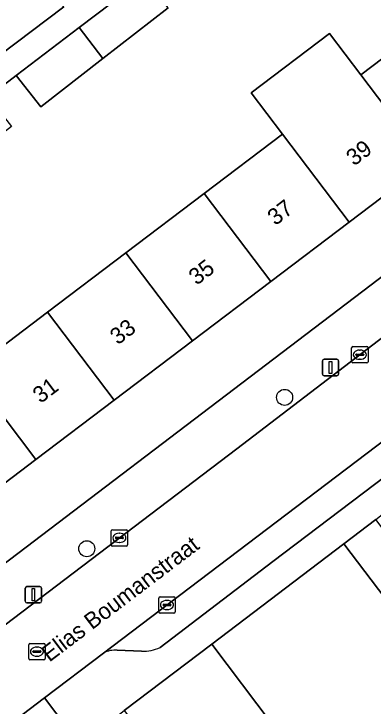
# Model space of a CAD drawing. Extents: x 160030 to 160839, y 385325 to 386450.
# Drawn here: x 160320.85 to 160342.79, y 385850.63 to 385892.89 of the extents above; entities that cross this region are included whole.
import ezdxf

# ---------------------------------------------------------------- set-up
doc = ezdxf.new("R2010")
doc.units = 0
for name, color, linetype in [('IMGEO_Boom', 7, 'Continuous'), ('IMGEO_Erf', 7, 'Continuous'), ('IMGEO_Groenvoorziening', 7, 'Continuous'), ('IMGEO_Kolk', 7, 'Continuous'), ('IMGEO_Lichtmast', 7, 'Continuous'), ('IMGEO_Muur', 7, 'Continuous'), ('IMGEO_Openbare_ruimte_label', 7, 'Continuous'), ('IMGEO_Pand', 7, 'Continuous'), ('IMGEO_Pand_nummerreeks', 7, 'Continuous'), ('IMGEO_Parkeervlak_open', 7, 'Continuous'), ('IMGEO_Rijbaan_lokaal_open', 7, 'Continuous'), ('IMGEO_Rioolput', 7, 'Continuous'), ('IMGEO_Voetpad_open', 7, 'Continuous')]:
    doc.layers.add(name, color=color, linetype=linetype)

msp = doc.modelspace()

# ---------------------------------------------------------------- linework, layer by layer
at = {"layer": 'IMGEO_Boom'}
for centre in [(160337.388, 385869.482), (160325.309, 385860.242)]:
    msp.add_circle(centre, 0.489, dxfattribs=at)
at = {"layer": 'IMGEO_Erf'}
for points in [[(160294.063, 385852.843), (160298.997, 385856.578), (160303.779, 385860.2), (160308.563, 385863.822), (160313.347, 385867.444), (160318.13, 385871.066), (160322.914, 385874.688), (160327.697, 385878.309), (160332.481, 385881.931), (160337.264, 385885.553), (160335.354, 385888.075), (160340.138, 385891.697), (160342.048, 385889.175), (160346.831, 385892.796), (160351.765, 385896.532)], [(160330.268, 385893.263), (160326.279, 385890.159), (160322.499, 385887.218), (160321.004, 385889.138), (160319.29, 385887.834), (160320.701, 385886.02), (160316.695, 385882.903), (160312.932, 385879.975), (160311.453, 385881.876), (160309.511, 385880.442), (160310.707, 385878.818), (160306.883, 385875.948), (160303.08, 385873.095), (160301.888, 385874.626), (160300.199, 385873.289), (160301.566, 385871.532), (160297.525, 385868.388)], [(160356.339, 385890.539), (160355.831, 385891.162), (160350.897, 385887.426), (160346.114, 385883.805), (160341.33, 385880.183), (160336.547, 385876.561), (160331.763, 385872.939), (160326.98, 385869.318), (160322.196, 385865.696), (160317.412, 385862.073), (160312.629, 385858.452), (160307.845, 385854.83), (160303.062, 385851.208), (160298.129, 385847.473), (160300.518, 385844.329), (160355.835, 385886.372)], [(160351.187, 385847.126), (160348.331, 385850.871), (160345.262, 385854.895), (160347.23, 385856.396), (160345.903, 385858.136), (160343.947, 385856.654), (160340.997, 385860.55), (160332.936, 385854.418), (160336.632, 385849.537)]]:
    msp.add_lwpolyline(points, dxfattribs=at)
at = {"layer": 'IMGEO_Groenvoorziening'}
msp.add_lwpolyline([(160321.143, 385833.325), (160328.543, 385823.58), (160338.075, 385830.835), (160322.717, 385851.129), (160316.136, 385846.137)], dxfattribs=at)
at = {"layer": 'IMGEO_Kolk'}
for p, q in [((160341.48, 385871.658), (160341.48, 385872.51)), ((160341.555, 385872.584), (160342.407, 385872.584)), ((160342.481, 385872.51), (160342.481, 385871.658)), ((160341.739, 385872.078), (160341.739, 385872.09)), ((160342.177, 385872.041), (160341.779, 385872.041)), ((160341.782, 385872.127), (160342.18, 385872.127)), ((160341.968, 385872.364), (160341.993, 385872.364)), ((160342.223, 385872.09), (160342.223, 385872.078)), ((160342.407, 385871.584), (160341.555, 385871.584)), ((160341.991, 385871.804), (160341.966, 385871.804)), ((160326.872, 385861.404), (160327.724, 385861.404)), ((160326.797, 385860.478), (160326.797, 385861.33)), ((160327.285, 385861.184), (160327.31, 385861.184)), ((160327.798, 385861.33), (160327.798, 385860.478)), ((160327.056, 385860.898), (160327.056, 385860.91)), ((160327.494, 385860.861), (160327.096, 385860.861)), ((160327.099, 385860.947), (160327.497, 385860.947)), ((160327.308, 385860.624), (160327.283, 385860.624)), ((160327.54, 385860.91), (160327.54, 385860.898)), ((160327.724, 385860.404), (160326.872, 385860.404)), ((160329.703, 385856.381), (160329.703, 385857.233)), ((160329.778, 385857.307), (160330.63, 385857.307)), ((160330.704, 385857.233), (160330.704, 385856.381)), ((160329.962, 385856.801), (160329.962, 385856.813)), ((160330.4, 385856.764), (160330.002, 385856.764)), ((160330.005, 385856.85), (160330.403, 385856.85)), ((160330.191, 385857.087), (160330.216, 385857.087)), ((160330.446, 385856.813), (160330.446, 385856.801)), ((160330.63, 385856.307), (160329.778, 385856.307)), ((160330.214, 385856.527), (160330.189, 385856.527))]:
    msp.add_line(p, q, dxfattribs=at)
for points in [[(160341.48, 385871.658), (160341.48, 385872.51)], [(160341.555, 385872.584), (160342.407, 385872.584)], [(160342.481, 385872.51), (160342.481, 385871.658)], [(160342.407, 385871.584), (160341.555, 385871.584)], [(160326.872, 385861.404), (160327.724, 385861.404)], [(160326.797, 385860.478), (160326.797, 385861.33)], [(160327.798, 385861.33), (160327.798, 385860.478)], [(160327.724, 385860.404), (160326.872, 385860.404)], [(160329.703, 385856.381), (160329.703, 385857.233)], [(160329.778, 385857.307), (160330.63, 385857.307)], [(160330.704, 385857.233), (160330.704, 385856.381)], [(160330.63, 385856.307), (160329.778, 385856.307)]]:
    msp.add_lwpolyline(points, dxfattribs=at)
for centre, radius, start, end in [((160341.557, 385872.508), 0.0765, 91.552, 178.448), ((160341.557, 385872.508), 0.0765, 91.552, 178.448), ((160342.405, 385872.508), 0.0765, 1.552, 88.448), ((160342.405, 385872.508), 0.0765, 1.552, 88.448), ((160341.779, 385872.087), 0.0403, 85.8775, 175.7526), ((160341.776, 385872.077), 0.0366, 178.938, 274.7102), ((160342.18, 385872.084), 0.043, 264.8664, 352.4533), ((160342.184, 385872.089), 0.0386, 1.7309, 96.639), ((160341.557, 385871.66), 0.0765, 181.552, 268.448), ((160341.557, 385871.66), 0.0765, 181.552, 268.448), ((160342.405, 385871.66), 0.0765, 271.552, 358.448), ((160342.405, 385871.66), 0.0765, 271.552, 358.448), ((160326.874, 385861.328), 0.0765, 91.552, 178.448), ((160326.874, 385861.328), 0.0765, 91.552, 178.448), ((160327.722, 385861.328), 0.0765, 1.552, 88.448), ((160327.722, 385861.328), 0.0765, 1.552, 88.448), ((160327.096, 385860.907), 0.0403, 85.8775, 175.7526), ((160327.093, 385860.897), 0.0366, 178.938, 274.7102), ((160327.497, 385860.904), 0.043, 264.8664, 352.4533), ((160327.501, 385860.909), 0.0386, 1.7309, 96.639), ((160326.874, 385860.48), 0.0765, 181.552, 268.448), ((160326.874, 385860.48), 0.0765, 181.552, 268.448), ((160327.722, 385860.48), 0.0765, 271.552, 358.448), ((160327.722, 385860.48), 0.0765, 271.552, 358.448), ((160329.78, 385857.231), 0.0765, 91.552, 178.448), ((160329.78, 385857.231), 0.0765, 91.552, 178.448), ((160330.628, 385857.231), 0.0765, 1.552, 88.448), ((160330.628, 385857.231), 0.0765, 1.552, 88.448), ((160330.002, 385856.81), 0.0403, 85.8775, 175.7526), ((160329.999, 385856.8), 0.0366, 178.938, 274.7102), ((160330.403, 385856.807), 0.043, 264.8664, 352.4533), ((160330.407, 385856.812), 0.0386, 1.7309, 96.639), ((160329.78, 385856.383), 0.0765, 181.552, 268.448), ((160329.78, 385856.383), 0.0765, 181.552, 268.448), ((160330.628, 385856.383), 0.0765, 271.552, 358.448), ((160330.628, 385856.383), 0.0765, 271.552, 358.448)]:
    msp.add_arc(centre, radius, start, end, dxfattribs=at)
for centre, major_axis, ratio, start_param, end_param in [((160341.967, 385872.084), (-0.387, 0.002), 0.722429, 4.712389, 7.853982), ((160341.992, 385872.084), (-0.39, 0.002), 0.717154, 1.570796, 4.712389), ((160327.284, 385860.904), (-0.387, 0.002), 0.722429, 4.712389, 7.853982), ((160327.309, 385860.904), (-0.39, 0.002), 0.717154, 1.570796, 4.712389), ((160330.19, 385856.807), (-0.387, 0.002), 0.722429, 4.712389, 7.853982), ((160330.215, 385856.807), (-0.39, 0.002), 0.717154, 1.570796, 4.712389)]:
    msp.add_ellipse(centre, major_axis=major_axis, ratio=ratio, start_param=start_param, end_param=end_param, dxfattribs=at)
at = {"layer": 'IMGEO_Lichtmast'}
for p, q in [((160339.696, 385870.903), (160339.696, 385871.703)), ((160339.696, 385871.703), (160339.696, 385870.903)), ((160339.796, 385871.803), (160340.586, 385871.803)), ((160340.586, 385871.803), (160339.796, 385871.803)), ((160340.686, 385871.703), (160340.686, 385870.903)), ((160340.686, 385870.903), (160340.686, 385871.703)), ((160340.586, 385870.803), (160339.796, 385870.803)), ((160339.796, 385870.803), (160340.586, 385870.803)), ((160321.553, 385857.03), (160321.553, 385857.83)), ((160321.553, 385857.83), (160321.553, 385857.03)), ((160321.653, 385857.93), (160322.443, 385857.93)), ((160322.443, 385857.93), (160321.653, 385857.93)), ((160322.543, 385857.83), (160322.543, 385857.03)), ((160322.543, 385857.03), (160322.543, 385857.83)), ((160322.443, 385856.93), (160321.653, 385856.93)), ((160321.653, 385856.93), (160322.443, 385856.93))]:
    msp.add_line(p, q, dxfattribs=at)
for points in [[(160340.116, 385871.678), (160340.266, 385871.678), (160340.266, 385870.928), (160340.116, 385870.928), (160340.116, 385871.678)], [(160321.973, 385857.805), (160322.123, 385857.805), (160322.123, 385857.055), (160321.973, 385857.055), (160321.973, 385857.805)]]:
    msp.add_lwpolyline(points, dxfattribs=at)
for centre, start, end in [((160339.796, 385871.703), 90, 180), ((160339.796, 385871.703), 90, 180), ((160340.586, 385871.703), 0, 90), ((160340.586, 385871.703), 360, 90), ((160339.796, 385870.903), 180, 270), ((160339.796, 385870.903), 180, 270), ((160340.586, 385870.903), 270, 0), ((160340.586, 385870.903), 270, 0), ((160321.653, 385857.83), 90, 180), ((160321.653, 385857.83), 90, 180), ((160322.443, 385857.83), 0, 90), ((160322.443, 385857.83), 360, 90), ((160321.653, 385857.03), 180, 270), ((160321.653, 385857.03), 180, 270), ((160322.443, 385857.03), 270, 0), ((160322.443, 385857.03), 270, 0)]:
    msp.add_arc(centre, 0.1, start, end, dxfattribs=at)
at = {"layer": 'IMGEO_Muur'}
msp.add_lwpolyline([(160332.936, 385854.418), (160340.997, 385860.55)], dxfattribs=at)
at = {"layer": 'IMGEO_Pand'}
for points in [[(160323.907, 385893.322), (160322.315, 385895.423), (160318.397, 385892.456), (160319.975, 385890.373)], [(160328.841, 385895.097), (160324.843, 385892.056), (160326.279, 385890.159), (160330.268, 385893.263)], [(160346.831, 385892.796), (160342.048, 385889.175), (160346.114, 385883.805), (160350.897, 385887.426)], [(160326.279, 385890.159), (160324.843, 385892.056), (160321.004, 385889.138), (160322.499, 385887.218)], [(160342.048, 385889.175), (160340.138, 385891.697), (160335.354, 385888.075), (160337.264, 385885.553), (160341.33, 385880.183), (160346.114, 385883.805)], [(160337.264, 385885.553), (160332.481, 385881.931), (160336.547, 385876.561), (160341.33, 385880.183)], [(160331.763, 385872.939), (160336.547, 385876.561), (160332.481, 385881.931), (160327.697, 385878.309)], [(160327.697, 385878.309), (160322.914, 385874.688), (160326.98, 385869.318), (160331.763, 385872.939)], [(160322.196, 385865.696), (160326.98, 385869.318), (160322.914, 385874.688), (160318.13, 385871.066)], [(160317.412, 385862.073), (160322.196, 385865.696), (160318.13, 385871.066), (160313.347, 385867.444)], [(160340.997, 385860.55), (160343.947, 385856.654), (160345.903, 385858.136), (160342.953, 385862.032)], [(160327.586, 385850.367), (160331.281, 385845.487), (160336.632, 385849.537), (160332.936, 385854.418)]]:
    msp.add_lwpolyline(points, close=True, dxfattribs=at)
at = {"layer": 'IMGEO_Parkeervlak_open'}
for points in [[(160353.387, 385874.369), (160336.283, 385861.419), (160326.328, 385853.868)], [(160329.781, 385854.21), (160336.673, 385859.456), (160349.751, 385869.377)], [(160327.168, 385854.04), (160328.654, 385853.982)]]:
    msp.add_lwpolyline(points, dxfattribs=at)
for centre, radius, start, end in [((160328.761, 385856.354), 2.375, 267.4258, 295.4481), ((160327.019, 385852.631), 1.417, 83.9625, 119.1816)]:
    msp.add_arc(centre, radius, start, end, dxfattribs=at)
at = {"layer": 'IMGEO_Rijbaan_lokaal_open'}
for points in [[(160357.581, 385883.992), (160334.468, 385866.348), (160310.316, 385848.008)], [(160316.136, 385846.137), (160322.717, 385851.129), (160326.328, 385853.868), (160336.283, 385861.419), (160353.387, 385874.369), (160360.393, 385880.034)]]:
    msp.add_lwpolyline(points, dxfattribs=at)
at = {"layer": 'IMGEO_Rioolput'}
for p, q in [((160321.763, 385853.532), (160321.763, 385854.384)), ((160321.838, 385854.458), (160322.69, 385854.458)), ((160322.251, 385854.238), (160322.276, 385854.238)), ((160322.764, 385854.384), (160322.764, 385853.532)), ((160322.022, 385853.952), (160322.022, 385853.964)), ((160322.46, 385853.915), (160322.062, 385853.915)), ((160322.065, 385854.001), (160322.463, 385854.001)), ((160322.506, 385853.964), (160322.506, 385853.952)), ((160322.69, 385853.458), (160321.838, 385853.458)), ((160322.274, 385853.678), (160322.249, 385853.678))]:
    msp.add_line(p, q, dxfattribs=at)
for points in [[(160321.763, 385853.532), (160321.763, 385854.384)], [(160321.838, 385854.458), (160322.69, 385854.458)], [(160322.764, 385854.384), (160322.764, 385853.532)], [(160322.69, 385853.458), (160321.838, 385853.458)]]:
    msp.add_lwpolyline(points, dxfattribs=at)
for centre, radius, start, end in [((160321.84, 385854.382), 0.0765, 91.552, 178.448), ((160321.84, 385854.382), 0.0765, 91.552, 178.448), ((160322.688, 385854.382), 0.0765, 1.552, 88.448), ((160322.688, 385854.382), 0.0765, 1.552, 88.448), ((160322.062, 385853.961), 0.0403, 85.8775, 175.7526), ((160322.059, 385853.951), 0.0366, 178.938, 274.7102), ((160322.463, 385853.958), 0.043, 264.8664, 352.4533), ((160322.467, 385853.963), 0.0386, 1.7309, 96.639), ((160321.84, 385853.534), 0.0765, 181.552, 268.448), ((160321.84, 385853.534), 0.0765, 181.552, 268.448), ((160322.688, 385853.534), 0.0765, 271.552, 358.448), ((160322.688, 385853.534), 0.0765, 271.552, 358.448)]:
    msp.add_arc(centre, radius, start, end, dxfattribs=at)
for centre, major_axis, ratio, start_param, end_param in [((160322.25, 385853.958), (-0.387, 0.002), 0.722429, 4.712389, 7.853982), ((160322.275, 385853.958), (-0.39, 0.002), 0.717154, 1.570796, 4.712389)]:
    msp.add_ellipse(centre, major_axis=major_axis, ratio=ratio, start_param=start_param, end_param=end_param, dxfattribs=at)
at = {"layer": 'IMGEO_Voetpad_open'}
for points in [[(160323.907, 385893.322), (160319.975, 385890.373), (160318.082, 385888.879), (160314.348, 385886.052), (160310.44, 385883.093), (160308.6, 385881.679), (160309.15, 385880.932), (160309.511, 385880.442), (160311.453, 385881.876), (160315.273, 385884.78), (160319.29, 385887.834), (160321.004, 385889.138), (160324.843, 385892.056), (160328.841, 385895.097)], [(160355.835, 385886.372), (160300.518, 385844.329), (160299.39, 385843.472), (160301.695, 385840.441), (160302.585, 385841.09), (160333.469, 385800.262)], [(160310.316, 385848.008), (160334.468, 385866.348), (160357.581, 385883.992)], [(160326.797, 385849.728), (160327.586, 385850.367), (160332.936, 385854.418), (160340.997, 385860.55), (160342.953, 385862.032), (160344.216, 385863.016), (160346.224, 385864.537), (160351.36, 385868.446), (160353.782, 385870.28), (160354.522, 385870.841), (160353.622, 385872.023), (160361.189, 385877.731)], [(160351.421, 385870.644), (160349.751, 385869.377), (160336.673, 385859.456), (160329.781, 385854.21)], [(160326.328, 385853.868), (160322.717, 385851.129), (160338.075, 385830.835), (160338.558, 385830.197), (160329.027, 385822.942), (160330.354, 385821.202), (160339.895, 385828.507), (160340.379, 385827.87), (160348.315, 385817.419), (160348.774, 385816.814), (160348.92, 385816.623), (160349.301, 385816.12), (160349.785, 385815.482), (160352.475, 385811.94), (160355.177, 385808.382)], [(160328.654, 385853.982), (160327.168, 385854.04)]]:
    msp.add_lwpolyline(points, dxfattribs=at)
for centre, radius, start, end in [((160328.761, 385856.354), 2.375, 267.4258, 295.4481), ((160327.019, 385852.631), 1.417, 83.9625, 119.1816)]:
    msp.add_arc(centre, radius, start, end, dxfattribs=at)

# ---------------------------------------------------------------- texts
at = {"layer": 'IMGEO_Openbare_ruimte_label'}
msp.add_text('Elias Boumanstraat', height=1, rotation=37.1564, dxfattribs=at).set_placement((160323.022, 385853.288))
at = {"layer": 'IMGEO_Pand_nummerreeks'}
for s, rotation, p in [('39', 37.1334, (160341.629, 385883.569)), ('37', 37.1311, (160336.821, 385879.929)), ('35', 37.1311, (160332.012, 385876.289)), ('33', 37.1311, (160327.204, 385872.648)), ('31', 37.1311, (160322.486, 385869.076))]:
    msp.add_text(s, height=1, rotation=rotation, dxfattribs=at).set_placement(p)

doc.saveas('drawing.dxf')
